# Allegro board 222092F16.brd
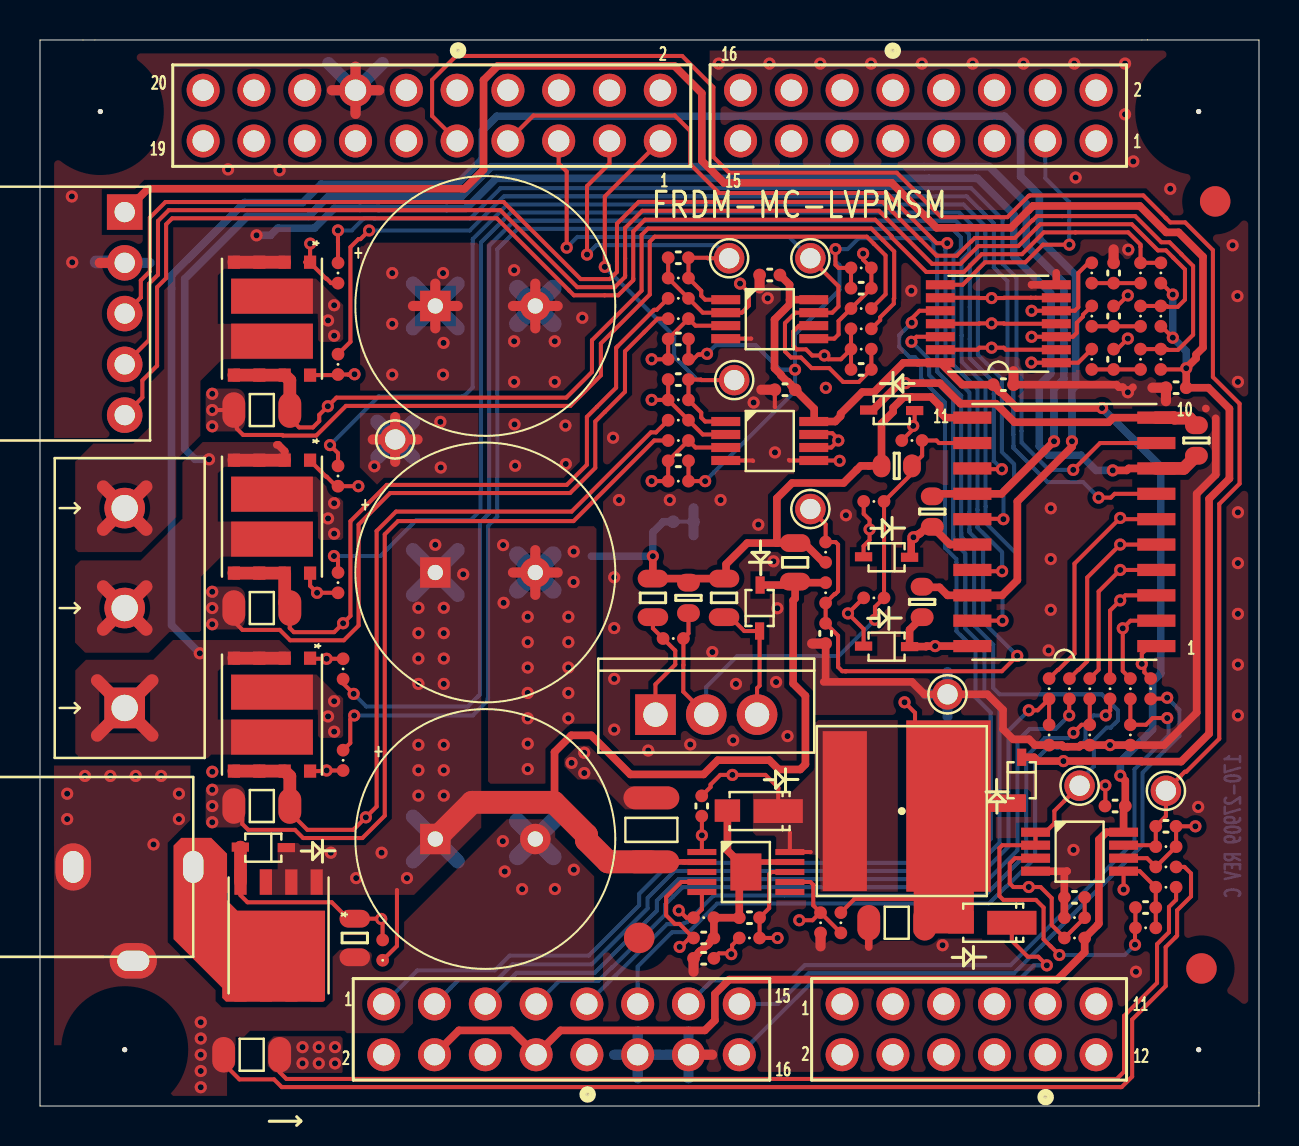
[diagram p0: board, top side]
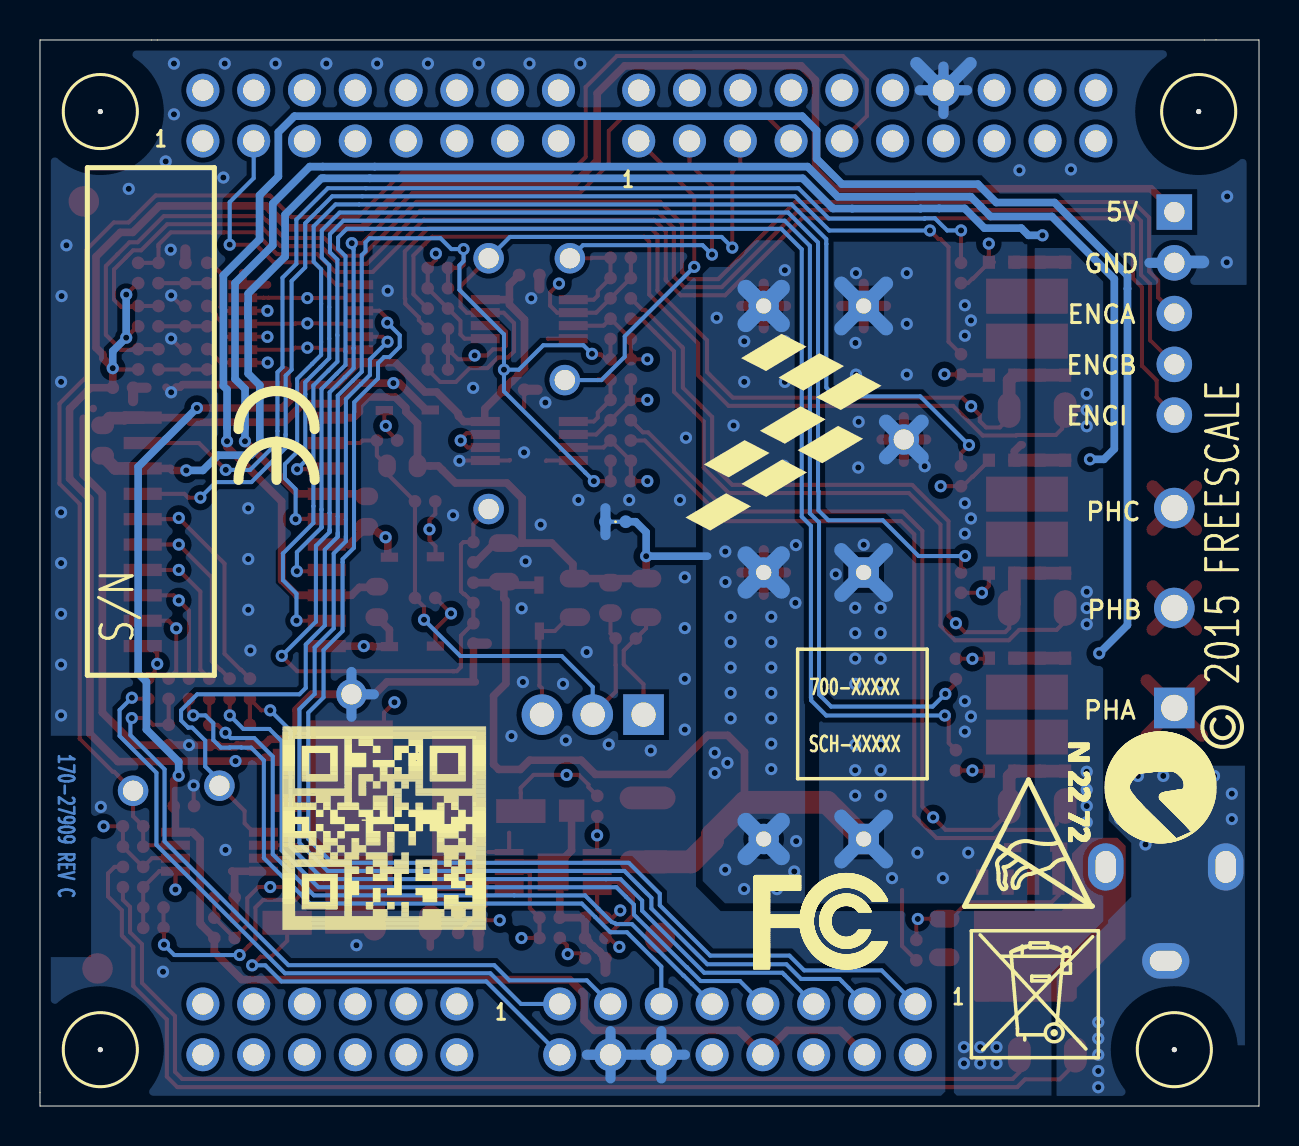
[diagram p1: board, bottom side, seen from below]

Outline 60.96 x 53.34 mm; copper layers: TOP, BOTTOM. Coordinates in mm from the lower left corner of the outline.
Outline path: 0,53.34 60.96,53.34 60.96,0 0,0 0,53.34

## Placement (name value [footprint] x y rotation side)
C1  220uF  [CAPRD_12P5X20MM]  22.27 40.03 0 top
C2  220uF  [CAPRD_12P5X20MM]  22.27 26.7 0 top
C3  220uF  [CAPRD_12P5X20MM]  22.27 13.36 0 top
C4  0.1uF  [CC0603_OV]  44.11 25.22 90 top
C5  0.1uF  [CC0603_OV]  44.62 29.74 90 top
C6  0.1uF  [CC0603_OV]  57.83 33.3 270 top
C7  0.01uF  [CC0402_25]  31.92 32.28 180 top
C8  0.01uF  [CC0402_25]  31.92 38.38 180 top
C9  0.01uF  [CC0402_25]  41.07 40.92 0 top
C10  0.1uF  [CC0603_OV]  42.84 32.03 180 top
C11  0.1uF  [CC0402_25]  36.49 41.58 180 top
C12  0.01uF  [CC0402_25]  31.92 36.35 0 top
C13  0.1uF  [CC0402_25]  37.26 35.84 180 top
C14  0.01uF  [CC0402_25]  31.92 42.44 0 top
C15  0.01uF  [CC0402_25]  41.07 36.86 0 top
C16  0.1uF  [CC0402_25]  51.73 10.44 180 top
C17  0.1uF  [CC0402_25]  39.29 23.65 270 top
C18  0.1uF  [CC0402_25]  53.77 15.01 180 top
C19  0.1uF  [CC0603_OV]  32.43 25.43 90 top
C20  0.1uF  [CC0805_OV]  34.21 25.43 90 top
C22  0.01uF  [CC0402_25]  55.29 9.93 0 top
C23  0.01uF  [CC0402_25]  56.31 14 180 top
C24  100pF  [CC0402_25]  53.69 37.36 90 top
C25  100pF  [CC0402_25]  53.69 39.52 90 top
C26  100pF  [CC0402_25]  53.69 41.68 90 top
C27  0.1uF  [CC0402_25]  56.81 35.94 180 top
C28  0.1uF  [CC0805_OV]  37.76 27.2 90 top
C29  0.1uF  [CC0402_25]  48.18 36.09 0 top
C35  0.1uF  [CC0402_25]  33.09 15.01 90 top
C36  6.8nF  [CC0402_25]  33.19 8.41 0 top
C37  1.8pF  [CC0402_25]  35.48 9.42 180 top
C38  820pF  [CC0402_25]  33.19 7.39 180 top
C39  2.2uF  [CC1210_OV]  30.58 13.82 90 top
C40  47uF  [CC1206_OV]  42.84 9.17 180 top
D1  1N914  [SODFL2513X100N]  42.59 34.82 0 top
D2  1N914  [SODFL2513X100N]  42.34 27.46 180 top
D3  1N914  [SODFL2513X100N]  42.34 22.99 180 top
D4  1N914  [SODFL2513X100N]  35.99 24.92 90 top
D5  DFLS1100  [SODFL3718X100N]  35.99 14.76 180 top
D6  MM3Z15VB  [SODFL2513X100N]  11.17 12.93 180 top
D7  DFLS1100  [SODFL3718X100N]  47.67 9.17 180 top
D8  1N914  [SODFL2513X100N]  49.09 16.3 270 top
J1  SSQ-108-03-G-D  [SAMTEC_SSQ-108-03-G-D]  52.81 48.29 180 top
J2  SSQ-110-03-G-D  [SAMTEC_SSQ-110-03-G-D]  31.02 48.29 180 top
J3  SSQ-108-03-G-D  [SAMTEC_SSQ-108-03-G-D]  17.19 5.11 0 top
J4  SSQ-106-03-G-D  [SAMTEC_SSQ-106-03-G-D]  40.11 5.11 0 top
J6  PJ-102AH  [CON_PJ-102AH]  7.66 11.96 0 top
J7  KRM03  [CON_KRM03]  4.24 24.92 270 top
J8  22-05-3051  [CON_22-05-3051]  4.24 44.73 90 top
L1  100uH  [IND_SRN8040]  43.1 14.76 0 top
NOREF  -  []  -418.71 -339.88 0 top
NOREF#2  -  [unnamed#2]  58.08 6.88 0 top
NOREF#3  -  []  4.24 2.82 0 top
NOREF#4  -  [unnamed#2]  29.97 8.41 0 top
NOREF#5  -  []  -43.63 -145.92 0 top
NOREF#6  -  []  59.6 0.01 90 top
NOREF#7  -  []  3.77 16.88 0 top
NOREF#8  -  []  -27.3 -36.7 0 top
NOREF#9  -  []  182.2 53.34 0 top
NOREF#10  -  []  0 53.34 0 top
NOREF#11  -  [unnamed#2]  58.77 45.26 0 top
NOREF#12  -  []  1.97 19.09 90 bottom
NOREF#13  -  []  14.38 2.42 180 bottom
NOREF#14  -  []  52.24 21.55 90 bottom
NOREF#15  -  [unnamed#2]  57.94 49.76 180 bottom
NOREF#16  -  []  49.13 33.93 180 bottom
NOREF#17  -  []  43.73 13.93 180 bottom
NOREF#18  -  []  -23.64 -7.57 180 bottom
NOREF#19  -  [unnamed#2]  3.02 49.76 180 bottom
NOREF#20  -  []  28.68 28.79 180 bottom
NOREF#21  -  [unnamed#2]  4.24 2.82 180 bottom
NOREF#22  -  [unnamed#2]  57.94 2.82 180 bottom
Q1  FDMS8090  [POWER56-10]  11.6 19.58 270 top
Q2  FDMS8090  [POWER56-10]  11.6 29.49 270 top
Q3  FDMS8090  [POWER56-10]  11.6 39.4 270 top
Q4  FDMS86163P  [POWER56-8]  11.93 8.53 270 top
R1  10  [RC0402_25]  43.61 33.3 180 top
R2  10  [RC0402_25]  41.7 30.25 180 top
R4  10  [RC0402_25]  15.16 21.87 90 top
R5  10  [RC0402_25]  14.9 31.52 270 top
R6  10  [RC0402_25]  14.9 41.68 270 top
R7  10  [RC0402_25]  41.7 25.43 180 top
R8  10  [RC0402_25]  15.16 17.3 270 top
R9  10  [RC0402_25]  14.9 26.19 270 top
R10  1K  [RC0402_25]  55.54 20.88 90 top
R11  1K  [RC0402_25]  54.53 20.88 90 top
R12  10  [RC0402_25]  14.9 37.11 270 top
R13  0.010  [RC1206_OV]  11.09 15.01 180 top
R14  0.010  [RC1206_OV]  11.09 24.92 180 top
R15  0.010  [RC1206_OV]  11.09 34.82 180 top
R16  1K  [RC0402_25]  53.51 20.88 90 top
R17  1K  [RC0402_25]  52.5 20.88 90 top
R18  1K  [RC0402_25]  51.48 20.88 90 top
R19  1K  [RC0402_25]  50.46 20.88 90 top
R20  20K  [RC0402_25]  31.92 31.27 180 top
R21  20K  [RC0402_25]  31.92 37.36 180 top
R22  20K  [RC0402_25]  41.07 41.94 0 top
R23  1K  [RC0402_25]  31.92 33.3 0 top
R24  1K  [RC0402_25]  31.92 39.4 0 top
R25  1K  [RC0402_25]  41.07 39.9 180 top
R26  1K  [RC0402_25]  31.92 34.32 0 top
R27  1K  [RC0402_25]  31.92 40.41 0 top
R28  1K  [RC0402_25]  41.07 38.89 180 top
R29  20K  [RC0402_25]  31.92 35.33 0 top
R30  20K  [RC0402_25]  31.92 41.43 0 top
R31  20K  [RC0402_25]  41.07 37.87 0 top
R32  10K  [RC0402_25]  51.73 8.41 180 top
R33  52.3K  [RC0402_25]  39.29 25.68 270 top
R34  10K  [RC0402_25]  51.73 9.42 180 top
R35  3K  [RC0402_25]  39.29 27.71 270 top
R36  0.010  [RC1206_OV]  10.59 2.57 180 top
R37  1K  [RC0402_25]  56.31 10.95 180 top
R38  1K  [RC0402_25]  56.31 11.96 180 top
R39  20K  [RC0402_25]  56.31 12.98 180 top
R40  20K  [RC0402_25]  55.29 8.92 0 top
R41  100K  [RC0402_25]  17.14 7.8 90 top
R45  294K  [RC0402_25]  33.19 9.42 0 top
R46  59K  [RC0402_25]  40.05 9.17 270 top
R47  2K  [RC0402_25]  52.6 37.36 90 top
R48  1K  [RC0402_25]  56.05 37.36 90 top
R49  100  [RC0402_25]  55.04 37.36 270 top
R50  2K  [RC0402_25]  52.6 39.52 90 top
R51  1K  [RC0402_25]  56.05 39.52 90 top
R52  100  [RC0402_25]  55.04 39.52 270 top
R53  1K  [RC0402_25]  56.05 41.68 90 top
R54  2K  [RC0402_25]  52.6 41.68 90 top
R55  100  [RC0402_25]  55.04 41.68 270 top
R56  200  [RC0402_25]  31.67 23.39 180 top
R57  2.15K  [RC0805_OV]  30.65 25.43 90 top
R58  10K  [RC0402_25]  39.03 9.17 270 top
R59  150K  [RC0402_25]  35.48 8.41 180 top
R60  22.6K  [RC0805_OV]  15.74 8.41 270 top
R70  4.7K  [RC0402_25]  54.53 18.57 270 top
R71  4.7K  [RC0402_25]  52.5 18.57 270 top
R72  4.7K  [RC0402_25]  50.46 18.57 270 top
SH1  0  [RC0402_25_CT]  32.18 29.24 180 bottom
TP1  TP  [TP_TH_040]  34.72 36.32 0 top
TP2  TP  [TP_TH_040]  34.46 42.42 0 top
TP3  TP  [TP_TH_040]  38.53 42.42 0 top
TP4  TP  [TP_TH_040]  51.99 16.03 0 top
TP5  TP  [TP_TH_040]  38.53 29.87 0 top
TP6  TP  [TP_TH_040]  56.31 15.77 0 top
TP7  TP  [TP_TH_040]  17.76 33.35 0 top
TP8  TP  [TP_TH_040]  45.38 20.6 180 top
U1  FAN7888  [SOIC127P1032X265-20N]  51.23 28.73 180 top
U2  FAN4852  [SOP65P490X110-8N]  51.99 12.73 0 top
U3  FAN4852  [SOP65P490X110-8N]  36.49 39.37 0 top
U4  FAN4852  [SOP65P490X110-8N]  36.49 33.27 0 top
U5  LM317AHV  [TO-220]  33.32 19.58 0 top
U6  74LVX14  [SOP65P640X120-14N]  47.92 39.14 180 top
U7  TPS54060  [SOP50P490X110-11N]  35.3 11.71 0 top

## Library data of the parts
C1-C3 = CAP_POL
C4-C20 C22-C29 C35-C40 = CAP_NP
D1-D4 D8 = 1N914BWS
D5 D7 = DFLS1100
D6 = MM3Z15VB
J1 J3 = CONN_2x8
J2 = CONN_2x10
J4 = CONN_2x6
J6 = PJ-102AH
J7 = KRM03
J8 = CON5
L1 = SRN8040
Q1-Q3 = FDMS8090
Q4 = FDMS86163P
R1 R2 R4-R41 R45-R60 R70-R72 = RES
SH1 = SH_RES
TP1-TP8 = TP
U1 = FAN7888
U2-U4 = FAN4852
U5 = LM317AHV
U6 = 74LVX14
U7 = TPS54060

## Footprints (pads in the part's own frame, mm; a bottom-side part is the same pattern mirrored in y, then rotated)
CAPRD_12P5X20MM
  rect 1.524x1.524 hole 0.762: 1(-2.5,0)
  round 1.524 hole 0.762: 2(2.5,0)
CC0402_25
  round 0.635 smd: 1(-0.508,0) 2(0.508,0)
CC0603_OV
  oval 0.889x1.143 smd: 1(-0.762,0) 2(0.762,0)
CC0805_OV
  oval 0.889x1.524 smd: 1(-0.965,0) 2(0.965,0)
CC1206_OV
  oval 1.143x1.778 smd: 1(-1.4,0) 2(1.4,0)
CC1210_OV
  oval 1.143x2.794 smd: 1(-1.6,0) 2(1.6,0)
CON_22-05-3051
  rect 1.778x1.778 hole 1.016: 1(0,0)
  round 1.778 hole 1.016: 2(-2.54,0) 3(-5.08,0) 4(-7.62,0) 5(-10.16,0)
CON_KRM03
  rect 2.032x2.032 hole 1.321: 1(5,0)
  round 2.032 hole 1.321: 2(0,0) 3(-5,0)
CON_PJ-102AH
  oval 1.778x2.362 hole 1.016x1.6: 1(0,0) 2(-6,0)
  oval 2.362x1.778 hole 1.6x1.016: 3(-3,-4.7)
IND_SRN8040
  rect 2.21x8.001 smd: 1(-2.85,0) 2(2.85,0)
POWER56-8
  rect 3.75x3.91 smd: (0.66,0)
  rect 1.27x0.61 smd: 1(-2.67,1.905) 2(-2.67,0.635) 3(-2.67,-0.635) 4(-2.67,-1.905) 5(2.67,-1.905) 6(2.67,-0.635) 7(2.67,0.635) 8(2.67,1.905)
POWER56-10
  rect 0.66x0.61 smd: 1(-2.825,1.905) 2(-2.825,0.635) 3(-2.825,-0.635) 4(-2.825,-1.905) 5(2.825,-1.905) 6(2.825,-0.635) 7(2.825,0.635) 8(2.825,1.905)
  rect 1.753x4.089 smd: 9(-1.125,0) 10(1.125,0)
RC0402_25
  round 0.635 smd: 1(-0.508,0) 2(0.508,0)
RC0402_25_CT
  round 0.635 smd: 1(-0.508,0) 2(0.508,0)
RC0805_OV
  oval 0.889x1.524 smd: 1(-0.965,0) 2(0.965,0)
RC1206_OV
  oval 1.143x1.778 smd: 1(-1.4,0) 2(1.4,0)
SAMTEC_SSQ-106-03-G-D
  round 1.651 hole 1.067: 1(0,0) 2(0,-2.54) 3(2.54,0) 4(2.54,-2.54) 5(5.08,0) 6(5.08,-2.54) 7(7.62,0) 8(7.62,-2.54) 9(10.16,0) 10(10.16,-2.54) 11(12.7,0) 12(12.7,-2.54)
SAMTEC_SSQ-108-03-G-D
  round 1.651 hole 1.067: 1(0,0) 2(0,-2.54) 3(2.54,0) 4(2.54,-2.54) 5(5.08,0) 6(5.08,-2.54) 7(7.62,0) 8(7.62,-2.54) 9(10.16,0) 10(10.16,-2.54) 11(12.7,0) 12(12.7,-2.54) 13(15.24,0) 14(15.24,-2.54) 15(17.78,0) 16(17.78,-2.54)
SAMTEC_SSQ-110-03-G-D
  round 1.651 hole 1.067: 1(0,0) 2(0,-2.54) 3(2.54,0) 4(2.54,-2.54) 5(5.08,0) 6(5.08,-2.54) 7(7.62,0) 8(7.62,-2.54) 9(10.16,0) 10(10.16,-2.54) 11(12.7,0) 12(12.7,-2.54) 13(15.24,0) 14(15.24,-2.54) 15(17.78,0) 16(17.78,-2.54) 17(20.32,0) 18(20.32,-2.54) 19(22.86,0) 20(22.86,-2.54)
SODFL2513X100N
  rect 0.864x0.457 smd: A(1.15,-0.025) C(-1.15,0)
SODFL3718X100N
  rect 1.27x1.118 smd: A(1.61,-0.025)
  rect 2.464x1.194 smd: C(-0.93,0)
SOIC127P1032X265-20N
  rect 1.905x0.61 smd: 1(-4.6,5.715) 2(-4.6,4.445) 3(-4.6,3.175) 4(-4.6,1.905) 5(-4.6,0.635) 6(-4.6,-0.635) 7(-4.6,-1.905) 8(-4.6,-3.175) 9(-4.6,-4.445) 10(-4.6,-5.715) 11(4.6,-5.715) 12(4.6,-4.445) 13(4.6,-3.175) 14(4.6,-1.905) 15(4.6,-0.635) 16(4.6,0.635) 17(4.6,1.905) 18(4.6,3.175) 19(4.6,4.445) 20(4.6,5.715)
SOP50P490X110-11N
  rect 1.448x0.305 smd: 1(-2.2,1) 2(-2.2,0.5) 3(-2.2,0) 4(-2.2,-0.5) 5(-2.2,-1) 6(2.2,-1) 7(2.2,-0.5) 8(2.2,0) 9(2.2,0.5) 10(2.2,1)
  rect 1.549x1.854 smd: 11(0,0)
SOP65P490X110-8N
  rect 1.448x0.457 smd: 1(-2.2,0.975) 2(-2.2,0.325) 3(-2.2,-0.325) 4(-2.2,-0.975) 5(2.2,-0.975) 6(2.2,-0.325) 7(2.2,0.325) 8(2.2,0.975)
SOP65P640X120-14N
  rect 1.448x0.457 smd: 1(-2.9,1.95) 2(-2.9,1.3) 3(-2.9,0.65) 4(-2.9,0) 5(-2.9,-0.65) 6(-2.9,-1.3) 7(-2.9,-1.95) 8(2.9,-1.95) 9(2.9,-1.3) 10(2.9,-0.65) 11(2.9,0) 12(2.9,0.65) 13(2.9,1.3) 14(2.9,1.95)
TO-220
  rect 2.032x2.032 hole 1.219: 1(-2.54,0)
  round 2.032 hole 1.219: 2(0,0) 3(2.54,0)
TP_TH_040
  round 1.524 hole 1.016: 1(0,0)
unnamed#2
  round 1.524 smd: (0,0)

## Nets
3V3: C11.1 C13.1 C18.1 C29.1 J3.4(B2) J3.8(B4) R32.1 U2.8(V+) U3.8(V+) U4.8(V+) U6.14(VCC)
5V: C27.1 D8.C J8.1 R48.1 R51.1 R53.1
5V5: C40.1 D7.A D8.A L1.2 R46.1
5V_OUT: D7.C J3.16(B8)
15V: C10.1 C19.1 R1.1 R2.1 R7.1 R56.1 U1.12(VDD) U5.2(OUT)
GND: C11.2 C13.2 C16.2 C17.2 C18.2 C24.2 C25.2 C26.2 C27.2 C29.2 C36.2 C37.2 C38.2 C40.2 D5.A J2.14(B7) J3.12(B6) J3.14(B7) J8.2 R34.2 R45.2 R58.2 R70.2 R71.2 R72.2 SH1.1 TP8.1(TP) U2.4(-IN) U3.4(-IN) U4.4(-IN) U4.5(+INB) U6.7(GND) U7.9(GND) U7.11(PAD)
GNDM: C1.2(MINUS) C2.2(MINUS) C3.2(MINUS) C10.2 C19.2 C20.2 C28.2 C39.2 J6.2 J6.3 R35.2 R36.2 R38.1 R57.2 R60.2 SH1.2 U1.11(GND)
ADC_MID: C7.1 C8.1 C9.1 C22.1 R20.1 R21.1 R22.1 R40.1 TP4.1(TP) U2.1(OUTA) U2.2(-INA)
CS_A_H: Q1.5(S13) Q1.6(S12) Q1.7(S11) R13.1 R26.1
CS_A_L: R13.2 R14.2 R15.2 R23.1 R24.1 R25.1 R36.1 R37.1
CS_B_H: Q2.5(S13) Q2.6(S12) Q2.7(S11) R14.1 R27.1
CS_C_H: Q3.5(S13) Q3.6(S12) Q3.7(S11) R15.1 R28.1
CUR_A: C12.2 J2.1(A1) R29.2 TP1.1(TP) U4.1(OUTA)
CUR_B: C14.2 J2.3(A2) R30.2 TP2.1(TP) U3.1(OUTA)
CUR_C: C15.2 J2.5(A3) R31.2 TP3.1(TP) U3.7(OUTB)
CUR_DCB: C23.2 J2.9(A5) R39.2 TP6.1(TP) U2.7(OUTB)
ENC_A: J3.3(A2) U6.12(Y)
ENC_B: J3.1(A1) U6.10(Y)
ENC_I: J1.3(A2) U6.8(Y)
HOA: R4.1 U1.19(HO1)
HOB: R5.1 U1.15(HO2)
HOC: R6.1 U1.9(HO3)
LOA: R8.1 U1.17(LO1)
LOB: R9.1 U1.13(LO2)
LOC: R12.1 U1.7(LO3)
PH_A: C4.2 J7.1 Q1.2(S11) Q1.3(S12) Q1.4(S13) Q1.10(D2) U1.18(VS1)
PH_B: C5.2 J7.2 Q2.2(S11) Q2.3(S12) Q2.4(S13) Q2.10(D2) U1.14(VS2)
PH_C: C6.2 J7.3 Q3.2(S11) Q3.3(S12) Q3.4(S13) Q3.10(D2) U1.8(VS3)
PWM_AB: J3.13(A7) R11.1 R70.1
PWM_AT: J3.15(A8) R10.1
PWM_BB: J3.9(A5) R17.1 R71.1
PWM_BT: J3.11(A6) R16.1
PWM_CB: J3.5(A3) R19.1 R72.1
PWM_CT: J3.7(A4) R18.1
VM: C1.1(PLUS) C2.1(PLUS) C3.1(PLUS) C28.1 C39.1 D4.A D6.C Q1.9(D2) Q2.9(D2) Q3.9(D2) Q4.1(S1) Q4.2(S2) Q4.3(S3) R33.1 R41.1 TP7.1(TP) U7.2(VIN)
VOLT_DCB: C17.1 J2.7(A4) R33.2 R35.1 TP5.1(TP)
N24033468: C4.1 D3.C U1.20(VB1)
N24033594: C5.1 D2.C U1.16(VB2)
N24033653: C6.1 D1.C U1.10(VB3)
N24035180: D1.A R1.2
N24035201: D2.A R2.2
N24035206: D3.A R7.2
N24035227: Q1.1(G2) R4.2
N24035245: Q1.8(G2) R8.2
N24035263: Q2.1(G2) R5.2
N24035281: Q2.8(G2) R9.2
N24035326: Q3.8(G2) R12.2
N24035327: Q3.1(G2) R6.2
N24038254: C7.2 R20.2 R23.2 U4.3(+INA)
N24038267: C12.1 R26.2 R29.1 U4.2(-INA)
N24039985: C8.2 R21.2 R24.2 U3.3(+INA)
N24039987: C14.1 R27.2 R30.1 U3.2(-INA)
N24040204: C9.2 R22.2 R25.2 U3.5(+INB)
N24040206: C15.1 R28.2 R31.1 U3.6(-INB)
N24055425: C16.1 R32.2 R34.1 U2.3(+INA)
N24056935: R18.2 U1.5(HIN3)
N24056936: R16.2 U1.3(HIN2)
N24056937: R10.2 U1.1(HIN1)
N24056938: R19.2 U1.6(LIN3)
N24056939: R17.2 U1.4(LIN2)
N24056940: R11.2 U1.2(LIN1)
N24071789: C22.2 R37.2 R40.2 U2.5(+INB)
N24071791: C23.1 R38.2 R39.1 U2.6(-INB)
N24077170: C24.1 R47.1 R49.2
N24077180: J8.3 R48.2 R49.1
N24077887: J8.4 R51.2 R52.1
N24077889: C25.1 R50.1 R52.2
N24077981: J8.5 R53.2 R55.1
N24077985: C26.1 R54.1 R55.2
N24134116: U4.6(-INB) U4.7(OUTB)
N24143304: R47.2 U6.1(A)
N24143313: R50.2 U6.3(A)
N24143316: R54.2 U6.5(A)
N24143319: U6.6(Y) U6.9(A)
N24143322: U6.4(Y) U6.11(A)
N24143325: U6.2(Y) U6.13(A)
N24161844: R56.2 R57.1 U5.1(ADJ)
N24161852: C20.1 D4.C U5.3(IN)
N24161961: J6.1 Q4.5(D1) Q4.6(D2) Q4.7(D3) Q4.8(D4)
N24167767: C35.1 U7.1(BOOT)
N24167797: C35.2 D5.C L1.1 U7.10(PH)
N24167831: R46.2 R58.1 U7.7(VSEN)
N24167847: R45.1 U7.5(RT)
N24167851: C36.1 U7.4(SS)
N24167871: C37.1 R59.1 U7.8(COMP)
N24167893: C38.1 R59.2
N24169531: D6.A Q4.4(G) R41.2 R60.1

Pads without a net: J1 1 2 4 5 6 7 8 9 10 11 12 13 14 15 16; J2 2 4 6 8 10 11 12 13 15 16 17 18 19 20; J3 2 6 10; J4 1 2 3 4 5 6 7 8 9 10 11 12; U7 3 6

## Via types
v1: diameter 0.61, hole 0.305, TOP to BOTTOM, 259 vias

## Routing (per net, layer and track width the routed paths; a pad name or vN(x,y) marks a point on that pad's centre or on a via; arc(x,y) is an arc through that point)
3V3: length 93.7
  TOP w0.381: 37.49,40.35 37.49,41.1 C11.1 ; 37.49,40.35 U3.8 ; 37.49,40.35 37.49,40.1 36.73,39.35 36.73,36.91 37.05,36.59 37.05,36.56 37.36,36.25 37.39,36.25 37.41,36.23 37.42,36.23 37.54,36.11 37.54,36.09 37.57,36.07 37.57,36.04 C13.1 38.72,34.89 38.72,34.27 U4.8 39.77,34.25 40.04,34.52 40.04,34.64 41.12,35.73 41.71,35.73 43.18,37.19 43.9,37.19 43.91,37.19 U6.14 46.12,36.09 C29.1 47.88,35.88 47.9,35.84 47.93,35.79 47.98,35.75 48.03,35.71 48.08,35.69 48.09,35.69 48.85,34.93 v1(53.11,34.93) ; v1(54.03,16.53) 54.27,16.28 C18.1 54.19,14.93 U2.8 53.33,13.7 52.95,13.33 52.95,9.13 52.88,9.06 52.88,9.05 R32.1 52.24,7.7 50.87,6.32 34.46,6.32 33.75,5.61 33.75,4.29 33.25,3.78 26.03,3.78 J3.8 23.59,3.78 20.95,3.78 J3.4
  BOTTOM w0.381: v1(53.11,34.93) 54.67,33.37 56.05,31.98 56.05,21.64 55.64,21.23 55.64,18.84 54.03,17.23 v1(54.03,16.53)
5V: length 109.6
  TOP w0.203: R51.1 56.08,39.01 v1(56.65,38.44) ; R53.1 56.08,41.17 v1(56.65,40.6) ; v1(57.32,36.92) 57.26,36.86 R48.1
  TOP w0.381: 56.65,38.45 v1(56.65,38.44) ; v1(56.65,40.6) 56.65,40.63 56.69,40.67 ; D8.C 49.71,17.45 49.9,17.26 v1(51.18,17.26) 55.07,17.26 55.1,17.23 57.07,17.23 58.46,18.63 58.46,30.38 59.48,31.39 59.48,34.89 58.43,35.94 C27.1 v1(57.32,36.92) 57.82,37.41 57.82,37.6 58.16,37.95 58.16,42.49 56.94,43.71 56.32,43.71 55,45.03 49.66,45.03 49.65,45.03 49.64,45.03 49.43,44.81 49.42,44.81 48.55,43.94 44.84,43.94 44.43,44.35 42.59,46.19 34.21,46.19 33.1,47.3 33.1,50.67 31.72,52.04 22.89,52.04 22.18,51.33 22.18,46.85 21.23,45.9 5.4,45.9 J8.1
  BOTTOM w0.381: v1(56.65,40.6) 56.65,40.6 v1(56.65,38.44) 57.32,37.77 v1(57.32,36.92)
5V5: length 5.7
  TOP w0.203: 43.86,10.36 40.74,10.36 R46.1 ; v1(43.23,20.2) 43.76,19.68 43.76,18.97
  TOP w0.635: 44.27,9.19 C40.1 ; 46.06,14.65 L1.2
5V_OUT: length 20.4
  TOP w0.203: D7.C 48.6,8.27 49.4,7.47 49.92,7.47 v1(50.35,7.04)
  BOTTOM w0.203: v1(50.35,7.04) 49.69,7.04 48.89,6.24 38.64,6.24 J3.16
15V: length 29.4
  TOP w0.203: C19.1 32.43,23.65 R56.1 32.18,22.07 32.17,22.05 32.17,20.73 U5.2 ; U1.12 44.96,33.17 44.83,33.3 R1.1 44.11,32.54 C10.1 43.61,31.65 42.21,30.25 42.21,25.43 41.76,24.97 v1(41.76,24.33)
  BOTTOM w0.203: U5.2 33.32,20.97 34.87,22.52 39.94,22.52 v1(41.76,24.33)
GND: length 112.3
  TOP w0.203: C24.2 53.87,37.87 v1(54.4,38.4) ; 36.76,34.97 36.75,34.98 C13.2 ; C25.2 53.87,40.03 v1(54.4,40.56) ; 37.45,32.33 37.48,32.3 U4.5 39.78,32.3 39.8,32.28 v1(39.99,32.28) ; U3.4 35.56,38.39 35.57,38.4 ; C18.2 53.28,15.03 v1(53.28,16.04) ; 35.66,32.27 35.63,32.3 U4.4
  TOP w0.279: U7.9 35.8,12.21
  TOP w0.305: 35.8,12.21 U7.11
  TOP w0.381: 49.59,41.1 49.59,41.09 U6.7 50.82,41.69 ; 54.66,35.97 v1(54.4,35.71) 54.15,35.97 53.96,35.97 53.83,36.09 C29.2 ; v1(54.4,40.56) 54.4,40.57 ; 51.23,11.62 C16.2 R34.2 ; C38.2 32.89,7.6 32.91,7.64 32.94,7.7 32.99,7.74 33.04,7.77 33.08,7.79 33.3,8.01 33.34,8.02 33.39,8.06 33.44,8.1 33.47,8.16 33.49,8.2 C36.2 R45.2 C37.2 34.97,11.38 U7.11 35.3,11.86 34.38,12.79 D5.A ; U2.4 49.79,11.75 51.36,11.75 51.36,11.75 ; 58.3,34.9 58.31,34.9 ; 39.19,21.22 43.61,21.22 44.23,20.6 TP8.1 47.38,20.6 48.16,19.82 48.16,18.85 48.66,18.35 49.46,18.35 49.75,18.06 R72.2 51.1,18.06 51.18,17.98 51.39,17.98 51.39,17.98 51.97,17.98 52.06,18.06 R71.2 v1(53.51,18.06) R70.2 56.22,18.06 57.84,19.69 57.84,30.63 58.79,31.58 58.79,34.41 ; 39.29,21.32 C17.2 ; 54.34,42.93 v1(54.42,42.85) ; v1(54.4,38.4) 54.4,38.43 ; 41.44,7.95 C40.2
  TOP w0.508: 35.99,40.91 C11.2 ; C29.2 48.69,36.77 ; 36.07,35.84 C13.2 ; 38.61,23.14 C17.2 ; 14.6,50.83 J2.14 ; J2.14 15.78,49.64 ; J2.14 16.96,50.83 ; J2.14 15.78,52.01 ; C26.2 53.69,42.86 ; 2.99,42.19 J8.2 ; 32.68,6.72 C38.2 ; J3.14 33.61,2.57 ; 55.63,35.94 C27.2 56.31,35.27 ; 39.03,7.99 R58.2
  BOTTOM w0.508: 14.6,50.83 J2.14 ; J2.14 15.78,49.64 ; J2.14 16.96,50.83 ; J2.14 15.78,52.01 ; 32.68,29.91 SH1.1 32.68,28.56 ; 31.25,2.57 J3.14 ; J3.14 33.61,2.57 ; J3.14 32.43,3.75 ; J3.14 32.43,1.38 ; TP8.1 45.38,21.72 ; TP8.1 45.38,19.48 ; TP8.1 44.27,20.6 ; J3.12 31.07,2.57 ; J3.12 28.71,2.57 ; J3.12 29.89,3.75 ; J3.12 29.89,1.38 ; 2.99,42.19 J8.2 5.48,42.19
  BOTTOM w0.635: 14.43,52.17 J2.14 17.13,52.17 ; 2.81,42.23 4.19,42.23 J8.2
  vias: v1(1.59,45.51) v1(1.61,42.21) v1(9.4,46.86) v1(11.98,46.82) v1(28.66,33.44) v1(28.71,26.45) v1(28.71,23.91) v1(28.71,21.37) v1(28.71,18.83) v1(28.96,30.32) v1(30.42,17.79) v1(31.5,30.32) v1(32.52,18.09) v1(33.62,22.71) v1(33.94,52.16) v1(34.04,30.32) v1(34.66,18.3) v1(34.8,21.12) v1(35.69,35.2) v1(35.92,29.09) v1(36.48,52.16) v1(36.39,40.42) v1(36.68,27.25) v1(36.75,32.7) v1(36.87,24.9) v1(36.81,21.22) v1(37.38,18.51) v1(39.02,52.16) v1(39.3,35.93) v1(40.3,29.56) v1(41.56,52.16) v1(43.57,40.79) v1(44.1,52.16) v1(45.14,8.05) v1(46.64,52.16) v1(49.18,52.16) v1(50.44,22.8) v1(50.55,29.91) v1(50.55,27.37) v1(50.55,24.83) v1(51.68,12.81) v1(51.72,52.16) v1(51.79,46.46) v1(54.26,52.16) v1(54.26,49.62) v1(54.67,47.26) v1(54.81,6.72) v1(56.52,45.89) v1(57.92,14.97) v1(59.64,43.07) v1(59.88,40.53) v1(59.91,36.23) v1(59.91,29.71) v1(59.91,27.17) v1(59.91,24.63) v1(59.91,22.09) v1(59.91,19.55)
GNDM: length 116
  TOP w0.203: R36.2 9.19,2.12 9.97,1.33 11.7,1.33 12.09,0.95 54.02,0.95 54.02,0.95 54.09,0.95 54.62,1.47 54.62,4.32 56.29,6 56.29,7.95 56.78,8.44 56.86,8.52 56.86,9.79 57.56,10.49 57.56,11.64 57.23,11.96 R38.1
  TOP w0.381: 36.85,28.17 36.85,30.41 37.61,31.17 40.18,31.17 40.84,31.83 41.04,32.03 41.45,32.03 41.45,32.03 C10.2 42.08,34.15 42.67,34.73 42.67,34.94 43.19,35.47 43.58,35.47 43.58,35.48 44.56,35.48 44.99,35.05 44.99,34.74 45.28,34.44 U1.11 ; 36.85,28.17 C28.2 38.21,28.17 39.18,27.2 R35.2 ; 36.85,28.17 36.85,28.17 35.37,28.17 34.31,27.11 34.31,26.49 C20.2 32.63,26.39 C19.2 32.23,26.39 R57.2 30.65,26.4 v1(30.65,27.51)
  TOP w0.508: C1.2 25.89,40.03 ; C1.2 24.77,38.91 ; C1.2 24.77,41.15 ; C1.2 23.65,40.03 ; 24.77,25.58 C2.2 ; C2.2 25.89,26.7 ; C2.2 24.77,27.81 ; C2.2 23.65,26.7
  BOTTOM w0.381: SH1.2 31.17,29.24 30.65,28.71 v1(30.65,27.51) 27.58,27.51
  BOTTOM w0.838: 23.88,14.25 C3.2 ; C3.2 25.66,14.25 ; C3.2 23.88,12.47 ; C3.2 25.66,12.47 ; 23.88,27.59 C2.2 ; C2.2 23.88,25.8 ; C2.2 25.66,25.8 ; C2.2 25.66,27.59 ; 23.88,40.92 C1.2 ; C1.2 25.66,40.92 ; C1.2 25.66,39.14 ; C1.2 23.88,39.14
  vias: v1(1.36,15.63) v1(1.36,14.36) v1(2.25,16.52) v1(3.52,16.52) v1(4.79,16.52) v1(5.68,13.09) v1(6.06,16.52) v1(6.95,15.63) v1(6.95,14.36) v1(8.04,4.19) v1(8.04,3.38) v1(8.04,2.57) v1(8.04,1.75) v1(8.04,0.94) v1(23.16,28.07) v1(23.18,25.18) v1(23.15,13.25) v1(23.24,11.73) v1(23.71,41.82) v1(23.71,38.27) v1(23.71,36.23) v1(23.73,34.11) v1(23.76,32.04) v1(24.11,10.85) v1(24.39,24.48) v1(24.39,23.21) v1(24.39,21.94) v1(24.39,20.67) v1(24.39,19.4) v1(24.39,18.13) v1(24.39,16.86) v1(25.74,38.27) v1(25.74,36.23) v1(25.75,10.86) v1(26.28,34.05) v1(26.3,32.12) v1(26.42,24.48) v1(26.42,23.21) v1(26.42,21.94) v1(26.42,20.67) v1(26.42,19.4) v1(26.58,17.17) v1(26.68,26.22) v1(26.69,27.74) v1(26.7,11.82) v1(27.12,39.44) v1(27.22,17.68) v1(27.22,16.66)
ADC_MID: length 85.7
  TOP w0.203: C9.1 R22.1 39.94,41.94 39.78,42.09 v1(39.78,42.88) ; v1(33.26,31.27) 33.26,31.27 R20.1 C7.1 ; C22.1 R40.1 54.76,8.89 v1(54.76,8.07) ; v1(50.98,7.56) 50.55,7.99 50.54,7.99 50.19,8.34 50.19,9.93 49.81,10.31 48.18,10.31 47.98,10.51 47.98,12.91 48.12,13.05 U2.2 U2.1 50.28,13.7 50.73,14.15 50.73,14.76 51.23,15.27 51.23,15.27 TP4.1 ; v1(33.36,37.64) 33.32,37.6 32.99,37.6 32.98,37.6 32.91,37.6 32.67,37.36 R21.1 C8.1
  BOTTOM w0.203: v1(37.76,36.84) 37.76,37.45 37.76,37.45 37.76,38.61 39.99,40.84 39.99,42.06 39.78,42.27 v1(39.78,42.88) 40.39,42.88 40.93,43.42 44.48,43.42 44.68,43.22 44.68,42.76 44.87,42.58 44.87,36.74 45.31,36.3 46.07,35.54 46.07,29.51 46.07,28.67 46.07,28.67 46.07,28.62 46.07,28.55 46.07,28.54 46.07,28.48 46.72,27.84 46.72,24.04 47.67,23.09 47.67,20.92 47.99,20.6 53.1,20.6 53.5,20.2 53.51,20.2 53.91,19.8 53.91,19.29 53.55,18.94 53.35,18.94 52.7,18.29 52.7,16.99 52.38,16.67 52.38,16.42 TP4.1 ; v1(37.76,36.84) 37.01,36.84 35.79,38.07 33.79,38.07 v1(33.36,37.64) ; v1(37.76,36.84) 37.76,35.76 33.69,31.7 v1(33.26,31.27) ; v1(54.76,8.07) 54.24,7.56 v1(50.98,7.56)
CS_A_H: length 40.6
  TOP w0.203: R26.1 30.8,33.71 30.55,33.71 26.58,29.74 17.81,29.74 16.83,28.77 16.83,14.98 v1(16.3,14.44) 15.67,13.82 13.37,13.82 12.49,14.69 R13.1
  TOP w0.635: R13.1 12.49,16.5 Q1.7 Q1.6 Q1.5
CS_A_L: length 172.4
  TOP w0.203: 11.99,2.56 R36.1 11.99,1.69 12.33,1.35 53.85,1.35 54.21,1.71 54.21,4.51 55.86,6.16 55.86,8.1 56.46,8.7 56.46,9.96 56.81,10.32 R37.1 ; R24.1 30.89,39.4 30.28,38.79 30.2,38.7 29.25,37.76 29.25,35.74 28.25,34.73 28.25,34.73 27.77,34.25 27.77,31.93 26.51,30.67 17.51,30.67 15.93,29.09 15.93,24.04 15.2,23.3 12.51,23.3 11.99,23.82 10.12,23.82 9.69,24.25 R14.2 ; R13.2 10.12,14.59 10.12,14.12 10.41,13.82 12.75,13.82 13.16,13.41 16.12,13.41 17.24,14.53 17.24,28.6 17.9,29.27 26.68,29.27 30.71,33.3 R23.1 ; v1(8.61,34.82) R15.2 9.85,34.67 9.85,33.89 10.16,33.58 10.23,33.58 10.23,33.58 12.12,33.58 12.15,33.55 13.82,33.55 15.3,35.03 26.52,35.03 28.05,36.56 28.05,38.16 30.49,40.6 30.49,43.25 30.74,43.5 41.34,43.5 41.7,43.14 42.28,42.56 42.28,40.61 R25.1
  vias: v1(8.61,35.64) v1(8.61,34.01) v1(8.61,25.73) v1(8.61,24.92) v1(8.61,24.1) v1(8.62,16.73) v1(8.61,15.82) v1(8.61,15.01) v1(8.61,14.2) v1(13.13,2.95) v1(13.13,2.13) v1(13.94,2.95) v1(13.94,2.13) v1(14.75,2.95) v1(14.75,2.13)
CS_B_H: length 36.7
  TOP w0.203: R14.1 12.49,24.91 12.49,23.91 12.69,23.71 14.71,23.71 v1(15.16,24.16) 15.53,24.52 15.53,29.26 17.34,31.08 26.34,31.08 27.35,32.09 27.35,34.48 27.85,34.98 27.85,34.98 28.81,35.94 28.81,37.93 28.87,38 30.68,39.8 30.68,39.8 30.71,39.84 30.84,39.84 R27.1
  TOP w0.635: Q2.5 Q2.6 Q2.7 12.24,25.17 R14.1
CS_C_H: length 46.9
  TOP w0.203: R15.1 12.49,34.42 12.96,33.95 13.65,33.95 13.96,34.27 13.96,34.58 v1(14.4,35.01) 14.83,35.45 26.32,35.45 27.6,36.73 27.6,38.32 30.08,40.8 30.08,43.59 30.4,43.9 41.57,43.9 42.14,43.33 42.72,42.76 42.72,40.41 42.7,40.39 42.7,40.15 42.01,39.46 42.01,39.33 R28.1
  TOP w0.635: R15.1 12.49,36.31 Q3.7 Q3.6 Q3.5
CUR_A: length 22.7
  TOP w0.203: 34.69,36.35 TP1.1 33.08,36.32 33.05,36.35 C12.2 R29.2 33.07,34.69 33.07,34.45 33.26,34.25 U4.1 ; v1(28.24,41.99) 28.24,45.51 J2.1
  BOTTOM w0.203: TP1.1 32.89,36.32 31.72,37.49 31.72,38.51 v1(28.24,41.99)
CUR_B: length 19.2
  TOP w0.203: TP2.1 33.39,42.42 33.37,42.44 C14.2 R30.2 33.07,40.79 33.07,40.54 33.26,40.35 U3.1 ; v1(27.36,42.6) 27.36,46.03 28.48,47.16 J2.3
  BOTTOM w0.203: v1(27.36,42.6) 27.83,43.07 33.81,43.07 TP2.1
CUR_C: length 32
  TOP w0.203: v1(26.34,42.95) 26.34,46.76 25.94,47.16 J2.5 ; TP3.1 39.93,41.01 39.93,40.01 39.62,39.7 U3.7 37.78,39.7 37.25,39.17 37.25,37.76 37.56,37.45 38.06,37.45 38.59,36.92 39.47,36.92 40.16,36.23 40.95,36.23 C15.2 R31.2
  BOTTOM w0.203: v1(26.34,42.95) 26.87,43.48 37.46,43.48 TP3.1
CUR_DCB: length 83.9
  TOP w0.203: J2.9 19.61,49.54 19.61,51.34 20.81,52.54 32.11,52.54 33.67,50.98 33.67,47.49 34.46,46.7 42.84,46.7 45.07,44.48 48.38,44.48 49.43,45.52 49.44,45.52 49.45,45.54 49.46,45.54 49.49,45.56 55.18,45.56 56.28,44.45 56.33,44.41 56.53,44.21 57.27,44.21 58.65,42.82 58.65,36.47 59.99,35.14 59.99,31.14 58.97,30.12 58.97,18.38 57.32,16.73 57.25,16.73 57.06,16.53 57.06,16.53 TP6.1 56.31,14.5 C23.2 R39.2 55.73,13.05 U2.7
ENC_A: length 60.4
  TOP w0.203: U6.12 43.83,38.49 v1(43.58,38.24)
  BOTTOM w0.203: v1(43.58,38.24) 44.46,37.36 44.46,36.57 44.91,36.13 45.66,35.37 45.66,29.34 45.66,29.34 45.66,28.5 45.66,28.45 45.66,28.38 45.66,28.26 46.27,27.65 46.27,23.9 47.22,22.94 47.22,20.62 47.99,19.86 47.99,13.17 46.58,11.76 32.83,11.76 31.73,11.76 30.39,10.42 30.39,9.89 27.59,7.09 23.63,7.09 22.9,6.36 20.97,6.36 20.85,6.23 20.53,5.91 20.53,5.9 J3.3
ENC_B: length 64.1
  TOP w0.203: v1(43.59,39.19) 43.59,39.4 43.98,39.79 U6.10
  BOTTOM w0.203: v1(43.59,39.19) 42.97,38.57 42.97,37.99 43.48,37.47 43.76,37.47 44.06,37.17 44.06,36.4 45.25,35.21 45.25,34.73 45.26,34.72 45.26,29.17 45.26,28.33 45.26,28.33 45.26,28.28 45.26,28.28 45.26,28.21 45.26,27.93 45.83,27.36 45.83,27.21 45.83,23.77 46.78,22.81 46.78,20.45 47.54,19.68 47.54,13.36 46.35,12.17 31.51,12.17 29.96,10.62 29.96,10.04 27.44,7.52 23.48,7.52 22.75,6.79 18.87,6.79 J3.1
ENC_I: length 13
  TOP w0.203: v1(51.47,43.1) 50.16,43.1 49.28,42.21 47.26,42.21 46.14,41.09 U6.8
  BOTTOM w0.203: v1(51.47,43.1) 51.47,45.23 50.27,46.43 J1.3
HOA: length 77.6
  TOP w0.203: v1(15.69,20.62) 15.16,21.15 R4.1 ; v1(48.13,24.29) 46.63,24.29 U1.19
  BOTTOM w0.203: v1(15.69,20.62) 16.32,19.99 21.4,19.99 21.91,20.5 22,20.59 22,29.2 22,29.2 22.46,29.66 22.46,43.04 23.72,44.3 45.79,44.3 46.46,43.63 46.46,42.72 46.09,42.35 46.09,38.57 46.09,37.25 46.53,36.8 47.29,36.05 47.29,30.02 47.29,29.17 48.81,27.65 48.81,26.31 48.13,25.64 v1(48.13,24.29)
HOB: length 61.1
  TOP w0.203: U1.15 46.64,29.38 48.16,29.38 v1(48.18,29.36) ; v1(14.5,33.07) 14.9,32.67 R5.1
  BOTTOM w0.203: v1(14.5,33.07) 16.94,35.51 21.11,35.51 21.22,35.55 21.24,35.55 21.24,35.56 21.64,35.95 21.64,43.13 21.64,43.14 21.64,43.38 23.37,45.11 45,45.11 46.18,45.11 47.27,44.02 47.27,42.24 46.9,41.87 46.9,40.14 46.9,40.14 46.9,38.23 46.9,38.23 46.9,37.58 47.35,37.14 48.1,36.38 48.1,35.45 48.1,32.73 48.71,32.12 48.71,31.4 48.18,30.87 v1(48.18,29.36)
HOC: length 55.8
  TOP w0.203: U1.9 53.01,33.17 v1(51.67,31.83) ; R6.1 14.9,43.2 14.9,43.2 v1(14.9,43.81)
  BOTTOM w0.203: v1(51.67,31.83) 51.06,31.83 51.06,31.83 50.46,31.83 49.09,33.2 49.09,33.77 49.09,36.72 48.83,36.97 48.83,41.44 48.14,42.14 48.14,44.35 46.57,45.92 44.67,45.92 23.03,45.92 21.51,44.4 16.72,44.41 16.71,44.42 16.2,44.42 15.6,43.81 v1(14.9,43.81)
LOA: length 74.9
  TOP w0.203: R8.1 15.52,18.16 15.52,19.34 v1(15.71,19.54) ; U1.17 46.69,26.76 v1(48.11,26.76)
  BOTTOM w0.203: v1(15.71,19.54) 21.64,19.54 22.39,20.29 22.39,20.41 22.41,20.43 22.41,29.03 22.87,29.49 22.87,42.87 23.89,43.89 45.62,43.89 46.05,43.46 46.05,42.89 45.68,42.52 45.68,37.75 45.68,37.75 45.68,37.08 46.13,36.63 46.13,36.63 46.88,35.88 46.88,29.85 46.88,29.85 46.88,29 46.88,29 46.88,28.95 46.88,28.94 48.11,27.71 v1(48.11,26.76)
LOB: length 62.7
  TOP w0.203: R9.1 14.9,27.32 v1(14.7,27.52) ; v1(48.1,31.86) 46.66,31.86 U1.13
  BOTTOM w0.203: v1(48.1,31.86) 47.69,32.27 47.69,35.62 47.69,35.62 47.69,36.22 46.94,36.97 46.5,37.41 46.5,38.4 46.5,38.4 46.5,39.97 46.5,39.97 46.5,42.08 46.87,42.45 46.87,43.81 45.98,44.7 23.55,44.7 22.05,43.21 22.05,30.78 22.03,30.76 22.03,29.8 21.54,29.31 18.82,29.31 17.02,27.52 v1(14.7,27.52)
LOC: length 59.3
  TOP w0.203: R12.1 15.53,38.24 15.53,42.98 15.93,43.38 16.03,43.38 v1(16.46,43.81) ; v1(52.94,30.44) 53.55,30.44 53.74,30.63 55.83,30.63
  BOTTOM w0.203: v1(52.94,30.44) 52.16,31.22 50.38,31.22 48.68,32.92 48.68,33.03 48.68,33.6 48.67,33.6 48.67,36.54 48.38,36.84 48.38,41.28 47.7,41.96 47.7,44.17 47.06,44.8 47.06,44.8 46.35,45.52 44.84,45.52 23.2,45.52 21.49,43.81 v1(16.46,43.81)
PH_A: length 106.7
  TOP w0.381: v1(51.61,33.26) 51.61,32.98 48.88,30.25 48.88,26.31 48.11,25.55 U1.18 45.39,25.55 44.99,25.95 44.14,25.95 C4.2
  TOP w0.635: 2.86,18.55 J7.1 ; J7.1 2.86,21.29 ; J7.1 5.61,18.55 ; J7.1 5.61,21.29 ; Q1.4 Q1.3 Q1.2
  BOTTOM w0.381: v1(7.99,22.65) 6.58,24.06 6.58,40.9 6.58,40.9 6.58,41.56 10.22,45.21 13.14,45.21 14.06,46.13 20.85,46.13 22.12,47.4 22.12,48.81 22.84,49.53 48.22,49.53 48.24,49.52 49.04,48.73 49.04,46.51 49.98,45.57 49.98,43.38 51.79,41.56 51.79,36.03 51.61,35.85 51.61,33.96 v1(51.61,33.26)
PH_B: length 84.8
  TOP w0.381: v1(50.71,33.26) 50.22,32.77 50.22,32.77 48.08,30.63 44.75,30.63 C5.2 ; Q2.2 12.24,32.76 11.92,33.08 11.84,33.08
  TOP w0.635: Q2.2 Q2.3 Q2.4 ; 3.16,25.99 J7.2 ; J7.2 3.16,23.85 ; J7.2 5.31,23.85 ; J7.2 5.31,25.99
  BOTTOM w0.381: v1(50.71,33.26) 50.71,33.96 50.7,33.97 50.7,35.88 51.2,36.38 51.2,41.18 49.32,43.06 49.32,45.15 47.47,47 46.81,47 22.57,47 21.06,45.49 17.17,45.49 17.16,45.5 14.47,45.5 14.41,45.5 13.91,45 13.91,44.99 13.43,44.51 10.36,44.51 7.24,41.39 7.24,32.88 7.75,32.36 v1(8.45,32.36)
PH_C: length 69.7
  TOP w0.381: v1(53.65,31.8) 54.34,31.8 54.44,31.9 U1.8
  TOP w0.635: Q3.4 Q3.3 Q3.2 ; J7.3 5.31,28.85 ; J7.3 5.31,30.99 ; J7.3 3.16,30.99 ; J7.3 3.16,28.85 ; U1.8 57.19,31.9 C6.2
  BOTTOM w0.381: v1(10.83,43.57) 11.53,43.57 11.89,43.93 13.73,43.93 14.72,44.91 15.99,44.91 16.92,44.91 16.93,44.9 20.34,44.9 20.34,44.91 21.3,44.91 21.36,44.96 21.36,44.96 22.82,46.42 44.46,46.42 46.89,46.42 48.7,44.6 48.7,42.5 50.55,40.65 50.55,40.12 50.56,40.11 50.56,39.47 50.55,39.46 50.55,36.65 49.97,36.07 49.97,33.02 50.42,32.56 52.05,32.56 52.81,31.8 v1(53.65,31.8)
PWM_AB: length 35.9
  TOP w0.203: v1(56.37,19.41) 55.65,19.41 55.31,19.08 R70.1 R11.1
  BOTTOM w0.203: v1(56.37,19.41) 56.44,19.34 56.44,18.55 54.73,16.85 54.73,13.24 48.54,7.05 38.24,7.05 37.48,6.29 33.61,6.29 J3.13
PWM_AT: length 32.7
  TOP w0.203: v1(56.37,20.43) 56.34,20.43 56.3,20.38 55.56,20.38 R10.1
  BOTTOM w0.203: v1(56.37,20.43) 56.98,19.82 56.98,18.52 55.14,16.68 55.14,13.07 48.71,6.64 38.44,6.64 36.91,5.11 J3.15
PWM_BB: length 35.1
  TOP w0.203: R17.1 R71.1 52.08,19.08 v1(51.68,18.68)
  BOTTOM w0.203: J3.9 28.37,6.12 28.37,6.12 28.77,6.53 28.78,6.53 28.79,6.54 31.36,9.1 32.14,9.1 32.19,9.14 32.37,9.21 33.03,9.86 33.7,10.54 37.25,10.54 37.25,10.54 47.26,10.54 49.32,12.6 49.32,17.49 50.24,18.41 51.42,18.41 v1(51.68,18.68)
PWM_BT: length 34.8
  TOP w0.203: v1(53.3,19.55) 53.3,19.56 53.52,19.79 53.52,20.36 R16.1
  BOTTOM w0.203: J3.11 29.89,6.98 31.61,8.69 32.43,8.69 33.2,9.46 33.87,10.13 47.46,10.13 48.31,10.98 48.37,11.01 49.76,12.41 49.76,17.3 50.4,17.93 50.88,17.93 50.9,17.95 51.47,17.95 51.48,17.93 51.91,17.93 52.29,18.31 52.29,19.15 52.69,19.55 v1(53.3,19.55)
PWM_CB: length 39.5
  TOP w0.203: v1(49.45,19.8) 49.89,19.8 R19.1 R72.1
  BOTTOM w0.203: J3.5 23.73,6.57 23.73,6.57 23.83,6.67 27.74,6.67 30.85,9.77 30.85,10.28 31.93,11.35 32.66,11.35 46.81,11.35 48.43,12.98 48.43,18.78 v1(49.45,19.8)
PWM_CT: length 37
  TOP w0.203: v1(51.47,19.55) 51.47,19.55 51.47,20.12 51.48,20.13 R18.1
  BOTTOM w0.203: J3.7 25.96,6.25 27.92,6.25 28.6,6.93 28.61,6.93 31.26,9.58 31.26,10.07 31.66,10.47 32.13,10.95 47.04,10.95 48.88,12.79 48.88,18.26 49.49,18.87 50.79,18.87 v1(51.47,19.55)
VM: length 81.9
  TOP w0.203: 17.85,10.8 17.85,10.8 17.85,8.01 R41.1
  TOP w0.279: C39.1 32.23,12.22 32.23,12.21 33.1,12.21 U7.2
  TOP w0.381: D4.A 37.59,26.07 C28.1 ; 25.7,15.2 25.73,15.23 25.73,17.71 26.57,18.55 27.57,18.55 29.52,16.59 33.19,16.59 33.9,17.3 36.47,17.3 36.94,16.84 38.02,16.84 38.28,17.1 38.28,20.52 37.66,21.14 37.66,25.3 37.76,25.4 C28.1 ; C28.1 37.81,26.19 R33.1
  TOP w0.508: 17.76,32.23 TP7.1 ; TP7.1 17.76,34.47 ; TP7.1 16.64,33.35 ; TP7.1 18.88,33.35 ; 19.77,38.91 C1.1 ; C1.1 20.89,40.03 ; C1.1 19.77,41.15 ; C1.1 18.65,40.03
  TOP w1.143: C3.1 21.6,15.2 25.7,15.2 27.33,13.56 27.33,13.29 28.4,12.22 C39.1
  BOTTOM w0.711: C1.1 20.89,38.91 ; C1.1 18.65,38.91 ; C1.1 18.65,41.15 ; C1.1 20.89,41.15 ; 16.87,32.46 TP7.1 ; TP7.1 18.65,32.46 ; TP7.1 18.65,34.24 ; TP7.1 16.87,34.24 ; 18.65,12.24 C3.1 ; C3.1 18.65,14.48 ; C3.1 20.89,12.24 ; C3.1 20.89,14.48 ; C2.1 20.89,25.58 ; C2.1 20.89,27.81 ; C2.1 18.65,27.81 ; C2.1 18.65,25.58
  vias: v1(14.4,39.31) v1(14.4,29.4) v1(14.4,19.49) v1(14.54,12.67) v1(14.71,40.07) v1(14.71,38.54) v1(14.71,30.16) v1(14.71,28.64) v1(14.71,20.26) v1(14.71,18.73) v1(15.81,11.4) v1(16.72,32.01) v1(17.08,12.67) v1(17.61,41.68) v1(17.61,39.14) v1(17.61,36.6) v1(18.35,11.4) v1(18.92,24.93) v1(18.92,23.66) v1(18.92,22.39) v1(18.92,21.12) v1(18.92,18.07) v1(18.92,16.8) v1(18.92,15.53) v1(19.77,28.08) v1(20.02,34.23) v1(20.04,31.95) v1(20.15,41.68) v1(20.18,38.18) v1(20.15,36.6) v1(20.19,24.93) v1(20.19,23.66) v1(20.19,22.39) v1(20.19,21.12) v1(20.19,18.07) v1(20.19,16.8) v1(20.19,15.53) v1(21.16,26.61)
VOLT_DCB: length 67
  TOP w0.203: v1(45.37,43.17) 44.84,43.17 42.34,45.68 33.96,45.68 32.52,47.12 32.52,48.79 31.75,49.56 24.67,49.56 J2.7 ; v1(48.87,22.52) 48.1,21.75 40.32,21.75 40.25,21.76 40.25,21.76 40.12,21.76 39.91,21.96 39.91,22.1 39.91,22.1 39.91,22.16 39.91,23.53 C17.1 R33.2 39.73,25.61 39.77,25.61 39.91,25.76 39.91,28.09 39.78,28.22 R35.1 39.29,29.11 TP5.1
  BOTTOM w0.203: v1(45.37,43.17) 45.37,42.96 45.28,42.87 45.28,37.92 45.28,36.91 45.72,36.47 46.48,35.71 46.48,29.68 46.48,28.84 46.48,28.79 46.48,28.79 46.48,28.71 47.16,28.03 47.16,24.23 v1(48.87,22.52)
N24033468: length 4.9
  TOP w0.381: C4.1 43.49,23.83 D3.C 44.31,22.99 44.34,23.01 v1(44.77,23.01) U1.20
N24033594: length 4.6
  TOP w0.381: D2.C 43.57,27.54 43.57,28.34 v1(43.68,28.46) 43.79,28.57 43.83,28.57 43.84,28.59 43.91,28.59 43.94,28.62 43.98,28.62 44.04,28.68 44.04,28.68 44.34,28.98 C5.1 45.51,28.09 U1.16
N24033653: length 18
  TOP w0.381: D1.C 41.64,34.82 42.99,36.17 v1(43.29,36.17) 45,36.17 46.03,35.14 47.81,35.14 48.73,34.21 53.44,34.21 53.67,34.44 U1.10
  TOP w0.635: C6.1 57.47,34.42 56.73,34.42 56.71,34.44 U1.10
N24035180: length 1.8
  TOP w0.203: D1.A 43.74,34.1 v1(43.67,34.03) 43.67,33.87 R1.2
N24035201: length 3
  TOP w0.203: R2.2 41.19,29.63 41.48,29.34 v1(41.48,28.85) 41.48,28.31 41.19,28.02 D2.A
N24035206: length 3.1
  TOP w0.203: R7.2 41.18,25.43 v1(40.41,24.65) 41.19,23.87 D3.A
N24035227: length 1.7
  TOP w0.203: 13.51,22.41 13.73,22.41 13.76,22.38 v1(14.33,22.38) R4.2
N24035245: length 1.7
  TOP w0.203: R8.2 v1(14.33,16.79) 14.15,16.79 14.12,16.76 13.51,16.76
N24035263: length 3
  TOP w0.203: v1(15.92,31.01) R5.2 14.81,31.01 14.34,31.49 14.3,31.49 13.51,32.29 13.51,32.31
N24035281: length 2.2
  TOP w0.203: R9.2 v1(13.86,25.68) 13.51,26.03 13.51,26.66
N24035326: length 2.4
  TOP w0.203: v1(15.73,36.61) 15.73,36.61 15.79,36.61 15.81,36.59 15.43,36.59 15.42,36.6 R12.2 14.87,36.57 13.51,36.57
N24035327: length 3
  TOP w0.203: v1(13.51,43.15) 13.51,43.14 13.51,42.22 ; 13.51,42.22 13.51,42.19 14.3,41.4 14.33,41.4 14.56,41.17 R6.2 ; 13.51,42.22 13.25,42.22
N24038254: length 5.3
  TOP w0.203: v1(30.59,31.27) R20.2 C7.2 R23.2 32.78,32.95 U4.3
N24038267: length 5.4
  TOP w0.203: R29.1 R26.2 33.15,33.6 U4.2 ; R29.1 C12.1 ; R29.1 v1(30.59,35.33)
N24039985: length 5.3
  TOP w0.203: U3.3 32.78,39.04 R24.2 C8.2 R21.2 v1(30.59,37.36)
N24039987: length 7.2
  TOP w0.203: C14.1 R30.1 R27.2 33.15,39.7 U3.2 35.1,39.7 35.45,40.05 35.45,40.71 v1(35.01,41.15)
N24040204: length 6.2
  TOP w0.203: v1(41.16,42.65) 41.16,42.35 R22.2 C9.2 R25.2 39.94,39.28 39.94,38.61 39.72,38.39 U3.5
N24040206: length 7.3
  TOP w0.203: C15.1 R31.1 ; R31.1 R28.2 ; R31.1 40.05,37.36 39.41,37.36 v1(39.22,37.55) 38.61,37.55 38.31,37.86 37.84,37.86 37.66,38.04 37.66,38.75 37.95,39.04 38.69,39.04 U3.6
N24055425: length 9.5
  TOP w0.203: C16.1 R34.1 R32.2 51.14,8.5 51.14,8.52 50.59,9.06 50.59,10.4 50.04,10.96 v1(49.45,10.96) 48.67,10.96 48.49,11.14 48.49,12.14 48.76,12.4 U2.3
N24056935: length 9.6
  TOP w0.203: U1.5 v1(54.02,28.09) 52.37,26.44 52.37,22.25 51.95,21.83 51.92,21.83 R18.2
N24056936: length 6.1
  TOP w0.203: U1.3 54.27,25.55 v1(54.02,25.3) 53.51,24.79 R16.2 53.51,21.36
N24056937: length 2.3
  TOP w0.203: U1.1 55.48,23.01 55.1,22.63 v1(55.1,22.12) 55.23,22 55.23,21.7 R10.2
N24056938: length 11.4
  TOP w0.203: R19.2 50.9,21.83 50.93,21.83 51.73,22.63 51.73,27.14 v1(54.02,29.43) 54.08,29.36 U1.6
N24056939: length 7.9
  TOP w0.203: U1.4 v1(54.02,26.82) 52.94,25.74 52.94,21.83 R17.2
N24056940: length 4.5
  TOP w0.203: R11.2 54.15,21.77 v1(54.15,23.9) 54.53,24.28 U1.2
N24071789: length 4.9
  TOP w0.203: v1(54.19,10.83) U2.5 54.99,11.75 R37.2 C22.2 R40.2
N24071791: length 5.2
  TOP w0.203: v1(57.78,14) C23.1 R39.1 R38.2 55.36,12.4 U2.6
N24077170: length 2.4
  TOP w0.203: R47.1 C24.1 R49.2
N24077180: length 71.8
  TOP w0.203: J8.3 5.04,40.46 5.04,40.46 5.04,41.31 5.49,41.76 5.49,44.45 6.27,45.23 6.95,45.23 23.18,45.23 27.04,41.38 28.5,41.38 28.85,41.73 28.85,42.24 28.85,44.15 29.94,45.24 42.14,45.24 44.05,43.33 44.84,42.55 45.85,42.55 46.56,43.26 46.57,43.26 46.75,43.43 48.76,43.43 49.16,43.84 49.16,43.85 49.63,44.32 49.64,44.32 49.64,44.32 49.65,44.32 49.85,44.53 51.12,44.53 51.12,44.53 54.77,44.53 56.08,43.22 56.48,43.22 57.08,42.62 57.08,42.61 57.66,42.03 57.66,38.59 56.91,37.83 56.39,37.83 56.36,37.87 R48.2 R49.1
N24077887: length 70.8
  TOP w0.203: R52.1 R51.2 56.35,40.03 56.39,39.99 56.9,39.99 57.26,40.35 57.26,41.86 56.67,42.44 56.67,42.45 56.31,42.81 55.91,42.81 54.6,44.12 50.03,44.12 49.82,43.91 49.81,43.91 48.93,43.03 46.92,43.03 46.03,42.14 44.61,42.14 41.95,44.79 30.12,44.79 29.26,43.93 29.26,42.41 29.26,42.41 29.26,41.57 29.26,41.56 29.26,41.49 28.74,40.97 26.87,40.97 23.01,44.83 6.44,44.83 5.9,44.28 5.9,41.59 5.45,41.14 5.45,38.32 5.45,38.32 J8.4
N24077889: length 2.4
  TOP w0.203: R52.2 C25.1 R50.1
N24077981: length 68
  TOP w0.203: J8.5 5.12,35.45 5.12,36.3 5.85,37.04 5.85,37.04 5.85,40.97 6.31,41.42 6.31,44.11 6.61,44.42 22.85,44.42 26.46,40.8 26.7,40.56 28.24,40.56 28.91,40.56 29.67,41.32 29.67,41.4 29.67,41.4 29.67,43.76 30.26,44.35 41.76,44.35 42.59,43.52 42.59,43.46 44.32,41.73 46.2,41.73 47.09,42.62 49.1,42.62 50.2,43.71 51.78,43.71 51.78,43.71 54.42,43.71 55.03,43.1 55.03,43 55.04,43 R55.1 R53.2
N24077985: length 2.4
  TOP w0.203: R54.1 C26.1 R55.2
N24134116: length 2.8
  TOP w0.203: U4.6 39.57,32.95 v1(39.92,33.3) 39.92,33.36 39.62,33.67 38.76,33.67 U4.7
N24143304: length 3.3
  TOP w0.203: R47.2 51.92,37.19 U6.1 49.77,37.19 49.77,37.2 v1(49.57,37.2)
N24143313: length 4
  TOP w0.203: R50.2 52.16,39.59 52.16,39.5 51.85,39.2 51.85,38.69 51.65,38.49 U6.3 49.81,38.49 49.8,38.49 v1(49.59,38.49)
N24143316: length 5
  TOP w0.203: R54.2 52.43,42.19 51.92,41.68 51.92,39.97 51.75,39.79 U6.5 49.78,39.79 49.78,39.79 v1(49.59,39.79)
N24143319: length 5.8
  TOP w0.203: U6.6 49.79,40.44 49.79,40.44 49.56,40.44 49.54,40.44 48.21,40.44 48.2,40.43 v1(47.59,40.43) 46.98,40.43 46.96,40.44 U6.9
N24143322: length 5.8
  TOP w0.203: U6.11 46.96,39.14 46.98,39.16 v1(47.59,39.16) 48.2,39.16 48.22,39.14 U6.4
N24143325: length 5.9
  TOP w0.203: U6.2 48.3,37.84 48.2,37.94 v1(47.59,37.94) 46.98,37.94 46.88,37.84 U6.13
N24161844: length 5.7
  TOP w0.203: U5.1 30.78,21.1 31.76,22.09 31.77,22.11 31.77,22.78 31.74,22.81 R56.2 30.65,23.9 R57.1
N24161852: length 6.3
  TOP w0.203: C20.1 34.52,24.46 35.22,23.77 D4.C 35.99,21.03 35.86,20.9 35.86,19.58
N24167767: length 1.8
  TOP w0.203: C35.1 33.1,14.5 v1(33.1,13.54) U7.1
N24167797: length 7.8
  TOP w0.203: D5.C 36.92,15.66 36.92,15.67 36.92,15.92 36.28,16.57 v1(34.63,16.57) 34.02,16.57 33.53,16.08 33.53,15.96 C35.2 ; 38.53,12.71 38.53,12.71 U7.10 37.5,13.67
N24167831: length 5.4
  TOP w0.203: v1(37.97,9.3) 38.63,9.3 39.02,9.68 R58.1 ; R58.1 R46.2 ; R58.1 38.67,10.04 38.67,11.07 38.53,11.21 U7.7
N24167847: length 2.4
  TOP w0.203: U7.5 33.1,9.84 R45.1 32.33,9.42 31.96,9.79 v1(31.94,9.79)
N24167851: length 5.7
  TOP w0.203: v1(31.99,7.96) 32.01,7.96 32.05,8 32.08,8 32.48,8.41 C36.1 31.98,9.11 31.75,9.11 31.31,9.55 31.31,10.45 32.07,11.21 U7.4
N24167871: length 5.4
  TOP w0.203: U7.8 36.57,11.71 36.46,11.6 36.46,9.9 C37.1 R59.1 v1(36.88,8.41)
N24167893: length 2
  TOP w0.203: R59.2 34.61,8.05 34.61,7.64 v1(34.57,7.6) 34.49,7.6 34.46,7.64 33.95,7.64 C38.1
N24169531: length 11
  TOP w0.203: R41.2 17.13,8.31 17.13,9.29 v1(17.06,9.36) 16.82,9.36 16.81,9.37 R60.1 15.41,9.37 14.59,10.19 10.38,10.19 10.03,10.54 Q4.4
  TOP w0.635: Q4.4 10.03,12.95 D6.A

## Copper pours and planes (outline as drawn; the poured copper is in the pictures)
5V5 on TOP (solid shape): 47.54,15.59 47.55,15.59 49.29,15.59 49.3,15.59 49.3,14.72 47.55,14.72 47.54,14.72 47.54,10.73 46.7,10.73 46.7,8.64 46.69,8.64 43.7,8.64 43.69,8.64 43.69,10.73 43.32,10.73 43.32,19.29 47.54,19.29
GND on TOP: 28.16,0.51 28.16,11.52 32.03,11.52 32.34,11.83 32.34,16.1 32.13,16.31 29.99,16.31 28.16,18.15 28.16,41.6 30.95,44.39 30.95,44.51 33.47,44.51 33.49,44.49 33.49,52.74 33.42,52.81 59.27,52.81 60.42,51.66 60.42,0.51 ; 4 cut-outs
GND on TOP: 0.7,33.43 0.7,52.67 19.77,52.67 19.93,52.51 19.93,49.17 21.64,47.47 21.67,47.47 21.73,47.41 21.73,46.9 20.83,46 5.3,46 5.22,45.92 5.22,33.81 4.84,33.43
GND on BOTTOM: 28.16,41.6 27.61,42.14 26.69,42.14 25.43,43.41 8.07,43.41 6.32,41.66 6.32,41.08 0.62,41.08 0.62,51.64 0.64,51.64 1.82,52.83 28.33,52.83 28.33,52.81 59.27,52.81 60.42,51.66 60.42,0.51 15.9,0.51 15.68,0.73 15.68,9.7 15.74,9.75 26.91,9.75 28.16,10.99 ; 10 cut-outs
GNDM on TOP: 27.83,28.88 27.69,29.01 22.52,29.01 22.4,28.9 22.4,16.25 22.52,16.13 25.25,16.13 25.28,16.16 25.28,17.86 26.56,19.13 27.83,19.13
GNDM on TOP: 31.56,14.85 29.26,14.85 27.78,16.33 26.89,16.33 26.23,17 26.23,17.37 26.88,18.03 27.46,18.03 29.47,16.01 31.46,16.01 31.59,15.88 31.59,14.88
GNDM on TOP: 22.8,35.6 26.19,35.6 26.98,36.39 27.82,37.23 27.82,40.75 27.79,40.77 26.81,40.77 24.26,43.33 22.55,43.33 22.34,43.12 22.34,35.7 22.69,35.7
GNDM on TOP: 22.78,31.34 26.32,31.34 27.2,32.22 27.2,34.55 27.08,34.68 22.36,34.68 22.36,31.31 22.75,31.31
GNDM on TOP: 6.39,8.19 8.5,6.08 8.78,5.8 8.78,5.26 9.1,4.94 14.29,4.94 14.64,5.29 14.64,7.47 14.98,7.82 15.89,7.82 15.97,7.73 17.68,7.73 18.19,8.25 18.19,9.18 23.35,14.34 25.14,14.34 25.76,13.72 25.76,13.44 27.71,11.49 27.71,6.14 27.67,6.18 19.7,6.18 18.65,5.14 18.65,4.13 18.17,3.64 15.35,3.64 15.23,3.77 10.51,3.77 9.76,3.02 9.76,2.05 9.42,1.71 9.42,1.71 9.35,1.64 9.35,0.51 9.36,0.51 6.65,0.51 4.12,3.04 0.7,3.04 0.7,13.02 0.7,13.03 0.7,17.04 7.52,17.04 7.52,14.3 7.51,14.29 6.39,13.18
GNDM on BOTTOM: 6.39,12.9 6.39,10.47 10.2,6.65 10.2,4.95 10.2,4.95 10.2,0.51 6.47,0.51 3.94,3.04 0.7,3.04 0.7,13.01 0.7,13.01 0.7,17.04 0.72,17.03 7.52,17.03 7.52,14.27 7.5,14.27 6.38,13.15 6.39,13.14 6.39,12.9
GNDM on BOTTOM: 22.7,41.63 22.7,10.14 22.7,10.14 26.7,10.14 27.82,11.26 27.82,12.21 27.82,12.22 27.82,41.63 27.47,41.99 26.5,41.99 25.18,43.31 23.79,43.31 23.51,43.03 23.47,43 23.05,42.8 23.05,41.99
CS_A_L on TOP: 8.61,35.9 8.4,35.82 8.29,35.62 8.29,34.07 8.37,33.84 8.6,33.75 9.84,33.75 10.13,33.91 10.26,34.21 10.26,35.42 10.13,35.75 9.82,35.9
CS_A_L on TOP: 8.61,16.08 8.4,16.01 8.29,15.81 8.29,14.26 8.37,14.02 8.6,13.94 9.84,13.94 10.13,14.1 10.26,14.4 10.26,15.61 10.13,15.93 9.82,16.08
CS_A_L on TOP: 8.61,25.99 8.4,25.91 8.29,25.72 8.29,24.16 8.37,23.93 8.6,23.84 9.84,23.84 10.13,24.01 10.26,24.31 10.26,25.51 10.13,25.84 9.82,25.99
CS_A_L on TOP: 11.31,2.08 11.31,3.11 11.68,3.49 15.03,3.49 15.13,3.38 15.13,1.7 15.09,1.66 11.73,1.66
CS_A_L on BOTTOM: 7.79,41.25 7.79,9.26 10.38,6.67 10.38,0.54 10.39,0.52 15.11,0.52 15.26,0.67 15.26,9.59 15.09,9.75 11.21,9.75 11.21,42.92 11.2,42.93 9.47,42.93
PH_A on TOP: 8.15,23.31 11.97,23.31 12.54,22.74 12.54,22.08 9.24,22.08 9.23,22.09 8.89,21.75 8.89,19.34 13.65,19.34 13.65,17.59 13.64,17.58 8.56,17.58 8.38,17.41 2.01,17.41 1.77,17.65 1.77,21.79 2.3,22.33 5.66,22.33 6.65,23.32 8.15,23.32
PH_B on TOP: 7.12,32.21 7.8,32.89 7.8,32.89 8.13,33.22 11.97,33.22 12.54,32.65 12.54,31.98 9.24,31.98 9.23,32 8.89,31.66 8.89,29.24 13.65,29.24 13.65,27.5 13.64,27.49 9.06,27.49 8.06,26.49 8.06,23.8 7.98,23.72 6.47,23.72 5.44,22.68 2.26,22.68 1.75,23.19 1.75,27.02 2.03,27.3 5.03,27.3 7.12,29.39
PH_C on TOP: 6.66,42.82 6.66,43.97 12.54,43.97 12.54,41.89 9.24,41.89 9.23,41.9 8.89,41.56 8.89,39.14 13.63,39.14 13.65,39.12 13.65,37.4 13.63,37.37 9.11,37.37 8.03,36.29 8.03,34.26 8.02,34.25 8.02,33.53 6.81,32.33 6.81,29.46 5.07,27.72 1.91,27.72 1.76,27.86 1.76,32.25 1.77,32.25 2.67,33.15 4.66,33.15 5.48,33.97 5.48,35.83 5.48,35.83 5.48,36.16 6.21,36.89 6.21,41.83 6.21,41.84 6.21,42.36
VM on TOP: 9.56,41.4 13.83,41.4 14.86,40.37 14.87,40.37 15.16,40.08 15.16,38.34 15.06,38.23 14,38.23 13.89,38.34 13.89,39.62 13.86,39.65 13.86,39.64 9.56,39.64 9.56,39.65
VM on TOP: 21.93,34.71 21.88,34.75 16,34.75 16,31.95 17.09,30.85 19.57,30.85 19.57,30.86 21.9,30.86 21.93,30.89
VM on TOP: 10.99,11.84 11.88,11.84 11.89,11.85 11.89,13.16 16.38,13.16 17.49,14.27 17.49,28.52 18,29.03 22.04,29.03 22.07,29 22.07,13.93 20.76,12.62 20.69,12.55 20.62,12.48 18.71,10.57 10.99,10.57 10.99,11.84
VM on TOP: 9.56,21.58 13.83,21.58 14.28,21.14 14.28,21.14 14.86,20.56 14.99,20.56 15.16,20.39 15.16,18.53 15.05,18.42 14,18.42 13.89,18.53 13.89,19.81 13.86,19.84 13.86,19.83 9.56,19.83 9.56,19.83
VM on TOP: 16.01,43.2 16.01,35.7 21.93,35.7 21.95,35.72 21.95,43.1 21.85,43.2
VM on TOP: 9.56,31.49 13.83,31.49 14.28,31.05 14.86,30.47 14.95,30.47 15.16,30.25 15.16,28.43 15.05,28.33 14,28.33 13.89,28.43 13.89,29.71 13.86,29.74 13.86,29.74 9.56,29.74 9.56,29.74
VM on BOTTOM: 22,10.13 22,43.25 11.59,43.25 11.59,43.25 11.59,10.13
N24161961 on TOP (solid shape): 9.35,12.62 9.35,10.65 9.35,10.65 9.35,10.3 9.87,9.78 14.25,9.78 14.25,5.3 14.17,5.22 9.3,5.22 9.11,5.41 9.11,5.91 6.68,8.35 6.68,13.03 7.06,13.42 8.3,13.42 8.3,13.42 8.56,13.42
N24167797 on TOP: 39,12.34 38.77,12.58 38.09,12.58 38.09,12.58 37.07,12.58 36.82,12.83 36.82,13.43 36.72,13.53 35.81,13.53 35.65,13.69 35.65,15.62 35.78,15.74 37.64,15.74 37.64,15.76 38.7,16.82 38.7,19.08 38.93,19.31 42.9,19.31 42.9,10.72 39.08,10.72 39.06,10.71 39,10.77

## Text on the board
BOTTOM: 170-27909 REV C | 2 OF 8 | SECONDARY SIDE
Ref Des/Assembly Bottom: SECONDARY ASSEMBLY
Board Geometry/Soldermask Bottom: 6 OF 8 | SECONDARY SOLDERMASK
Ref Des/Silkscreen Bottom: 700-XXXXX | SCH-XXXXX | 5V | PHB | PHC | GND | PHA | ENCA | ENCB | ENCI | 8 OF 8 | SECONDARY SILKSCREEN
User.Comments: 1 OF 1 | TEST PROBE | 1/1 | 1
TOP: 1 OF 8 | PRIMARY SIDE
Ref Des/Assembly Top: PRIMARY ASSEMBLY
Board Geometry/Soldermask Top: 3 OF 8 | PRIMARY SOLDERMASK
Ref Des/Silkscreen Top: 5 OF 8 | PRIMARY SILKSCREEN | FRDM-MC-LVPMSM
DIMENSION: THICK +/-10% | GRID ORIGIN | PRIMARY DATUM
BODY_CENTER: 16. BASIC GRID INCREMENT AT 1:1 IS .0001. | 17. SUPPLIER MARKINGS - ON SOLDER SIDE ONLY, WHERE SHOWN. | 1. THIS DRAWING SPECIFIES THE REQUIREMENTS FOR A | 2. THE PWB MUST BE LEAD FREE ASSEMBLY PROCESS COMPATIBLE AND MUST BE ABLE TO HANDLE | 3. BASE MATERIAL - LAMINATE AND PREPREG SHALL MEET IPC-4101B-26, 83 or 98 | 4. COPPER FOIL WEIGHT - SEE STACKUP DETAIL 'A' | 5. CHARACTERISTIC IMPEDANCE - NONE | 6. MINIMUM CONDUCTIVE WIDTH/SPACING TO BE .005"/.004" | 7. PLATING FINISH - BOTH SIDES LEAD FREE HASL OR IMMERSION TIN. NO NICKEL | 8. ALL THROUGH HOLE VIAS MAY BE PLATED SHUT. | 9. SOLDERMASK - ORANGE COLOR LPI SOLDERMASK  BOTH SIDES. | 10. SILKSCREEN - WHITE EPOXY INK, BOTH SIDES.  NO SILK ON PADS. | 11. ELECTRICAL TEST - 100% IPCD356. | 12. PRINTED WIRING BOARD IS TO BE INDIVIDUALLY BAGGED. | 13. DRC'S MUST BE RUN ON THE GERBER BEFORE BUILDING BOARDS, | UNLESS PRIOR APPROVAL IS GIVEN IN WRITING BY FREESCALE. | 14. TEARDROPS MAYBE ADDED AT THE FAB HOUSE TO ALL SIGNAL LAYERS. | 15. 2 SOLDER SAMPLES TO BE PROVIDED. | 18. THE PWB WILL BE MARKED AS LEAD FREE BY USE OF AN INK STAMP Pb | 19. THE PWB WILL BE MARKED AS LEAD FREE PROCESS COMPATIBLE BY USE OF AN INK STAMP 260 C | 21. FINISHED PCB MUST BE PANELIZED FOR ASSEMBLY ACCORDING TO CONTRACT MANUFACTURERS REQUIREMENTS. | 22. DO NOT PROVIDE SOLDERMASK CLEARANCES FOR THE SPECIFIC LOCATIONS | MODIFICATION OF SOLDERMASK IS NOT ALLOWED WITHOUT WRITTEN PERMISSION FROM FREESCALE. | WITH SPECIFICATION IPC-A-600 CLASS 2 (LATEST REVISION). | A MINIMUM OF 5 CYCLES AT 260 DEGREES CELSIUS FOR 10 SECONDS. | LEAVE SOLDERMASK AS THEY APPEAR ON CAD. | THE ADDITION OF RAILS AND .125' NON-PLATED TOOLING HOLES ARE AT THE DISCRETION OF | CONTRACT MANUFACTURER.PANELIZATION MUST BE APPROVED BY CONTRACT MANUFACTURER. | Tg - MUST BE GREATER THAN OR EQUAL TO 150 DEGREES CELSIUS. | Td - MUST BE GREATER THAN OR EQUAL TO 330 DEGREES CELSIUS. | - MUST BE UL RECOGNIZED AND MUST HAVE AN ID THAT CONFORMS TO UL94V-0 | PRINTED WIRING BOARD IN ACCORDANCE | 20. ALL PLATED AND NON-PLATED THROUGH HOLES ARE TO BE DRILLED AT PRIMARY DRILL STEP. | ALL HOLE LOCATION TOLERANCES ARE TO BE +/-.002 IN REFERENCE TO THE PRIMARY DATUM. | 16 | 17 | 8
PASTEMASK_TOP: 4 OF 8 | PASTEMASK TOP
User.5: 7 OF 8 | SECONDARY PASTEMASK
